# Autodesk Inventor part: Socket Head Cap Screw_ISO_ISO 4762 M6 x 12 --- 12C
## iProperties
Created: 2011-02
Part Number: Socket Head Cap Screw_ISO_ISO 4762 M6 x 12 --- 12C
Document SubType Name: Modeling
Designer: eric
Density: 1 g/cm^3
Author: eric
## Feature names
1. Base1
